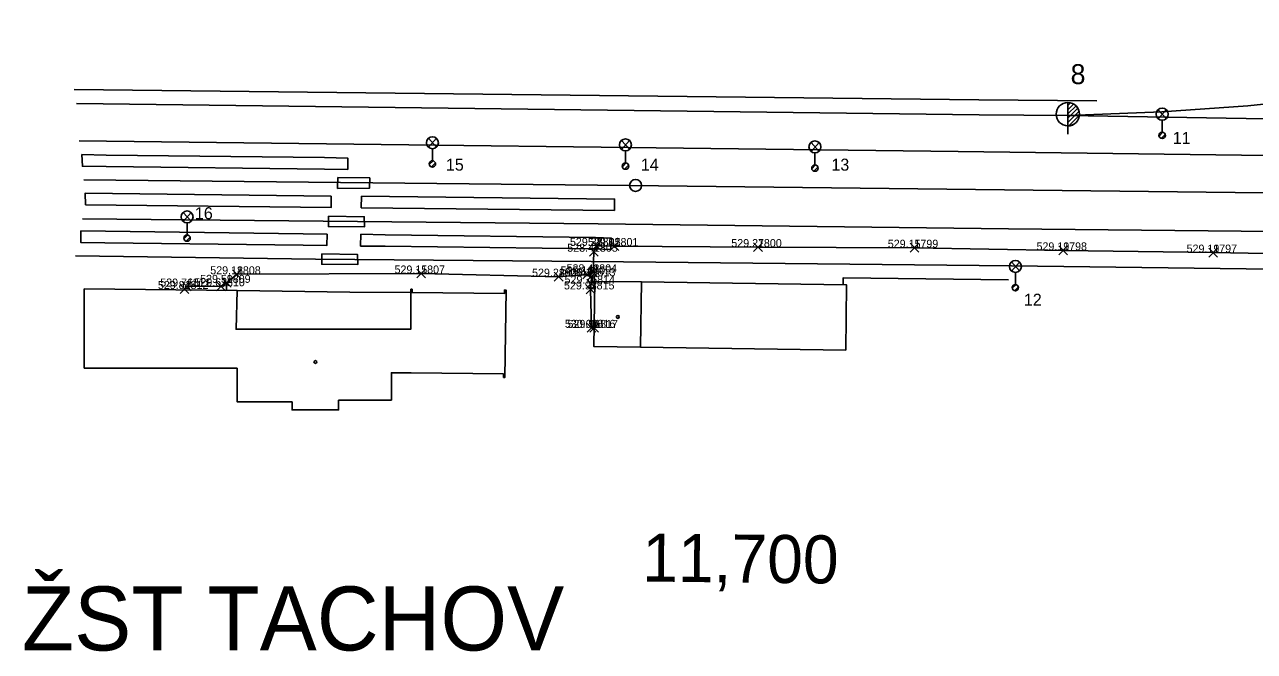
# Model space of a CAD drawing. Extents: x -874058 to -854960, y -10531873 to -1049126.
# Drawn here: x -874058 to -873904.3, y -1055491.8 to -1055413.5 of the extents above; entities that cross this region are included whole.
import ezdxf

# ---------------------------------------------------------------- set-up
doc = ezdxf.new("R2010")
doc.units = 0
for name, color, linetype in [('Vrstva 1', 7, 'Continuous'), ('Vrstva 13', 7, 'Continuous'), ('Vrstva 2', 7, 'Continuous'), ('Vrstva 23', 7, 'Continuous'), ('Vrstva 25', 7, 'Continuous'), ('Vrstva 28', 7, 'Continuous'), ('Vrstva 32', 7, 'Continuous'), ('Vrstva 35', 7, 'Continuous'), ('Vrstva 51', 7, 'Continuous'), ('Vrstva 52', 7, 'Continuous'), ('Vrstva 57', 7, 'Continuous'), ('Vrstva 60', 7, 'Continuous'), ('Vrstva 61', 7, 'Continuous'), ('Vrstva 7', 7, 'Continuous')]:
    doc.layers.add(name, color=color, linetype=linetype)

msp = doc.modelspace()

# ---------------------------------------------------------------- linework, layer by layer
at = {"layer": 'Vrstva 1'}
for points in [[(-873815.18, -1055413.48), (-873832.55, -1055415.22), (-873845.62, -1055416.69), (-873859.57, -1055418.29), (-873878.44, -1055420.61), (-873894.93, -1055422.54), (-873905.16, -1055423.61), (-873915.91, -1055424.4), (-873927.58, -1055424.84), (-873938.71, -1055424.74)], [(-873938.71, -1055424.74), (-874051.5, -1055423.34)], [(-873927.58, -1055424.84), (-873900.45, -1055425.31), (-873892.13, -1055425.7), (-873880.59, -1055426.63), (-873873.55, -1055427.3), (-873854.79, -1055429.58), (-873843.62, -1055431.39), (-873833.71, -1055432.56), (-873816.9, -1055434.47), (-873807.04, -1055435.55), (-873783.51, -1055438.28), (-873772.32, -1055439.75), (-873753.41, -1055441.11), (-873741.16, -1055441.25), (-873729.15, -1055441.64)], [(-874051.14, -1055428), (-873941.33, -1055429.34)], [(-873941.33, -1055429.34), (-873899.48, -1055429.88), (-873880.58, -1055430.11), (-873854.97, -1055431.05), (-873833.71, -1055432.56)], [(-874050.57, -1055432.88), (-873982.4, -1055433.59), (-873820.31, -1055435.48)], [(-873753.41, -1055441.11), (-873775.14, -1055440.87), (-873797, -1055440.56), (-873819.76, -1055440.22), (-873860.62, -1055439.87), (-873897.65, -1055439.39), (-873935.07, -1055438.98), (-873986.31, -1055438.38), (-874050.76, -1055437.73)], [(-873737.8, -1055445.87), (-873747.46, -1055445.67), (-873767.6, -1055445.41), (-873858.85, -1055444.62), (-873898.81, -1055444.08), (-873934.67, -1055443.63), (-873987.18, -1055443.07), (-874021.63, -1055442.79), (-874051.6, -1055442.39)]]:
    msp.add_lwpolyline(points, dxfattribs=at)
at = {"layer": 'Vrstva 13'}
for points in [[(-874051.78, -1055421.58), (-873938.77, -1055422.88), (-873924.01, -1055422.99)], [(-873935.05, -1055445.37), (-873955.72, -1055445.13), (-873955.72, -1055446)]]:
    msp.add_lwpolyline(points, dxfattribs=at)
at = {"layer": 'Vrstva 2'}
for p, q in [((-873927.64, -1055426.14), (-873927.64, -1055423.21)), ((-873927.64, -1055423.21), (-873927.64, -1055426.14)), ((-873927.64, -1055423.59), (-873927.31, -1055423.26)), ((-873927.64, -1055424.12), (-873926.92, -1055423.41)), ((-873927.64, -1055424.65), (-873926.62, -1055423.63)), ((-873927.64, -1055425.19), (-873926.39, -1055423.93)), ((-873927.64, -1055425.72), (-873926.23, -1055424.3)), ((-873927.64, -1055426.14), (-873927.64, -1055427.17)), ((-873927.64, -1055426.14), (-873927.64, -1055426.14)), ((-873927.53, -1055426.13), (-873926.19, -1055424.79))]:
    msp.add_line(p, q, dxfattribs=at)
msp.add_circle((-873927.64, -1055424.67), 1.46, dxfattribs=at)
msp.add_arc((-873927.64, -1055424.68), 1.46, 270.0196, 89.9804, dxfattribs=at)
at = {"layer": 'Vrstva 23'}
for points in [[(-873980.92, -1055445.64), (-873986.75, -1055445.59), (-873986.85, -1055453.72), (-873981.04, -1055453.8), (-873980.92, -1055445.64)], [(-873955.4, -1055454.17), (-873955.28, -1055446.01), (-873980.92, -1055445.64)], [(-874031.4, -1055446.72), (-874050.55, -1055446.49)], [(-874009.74, -1055446.97), (-874017.33, -1055446.9), (-874031.4, -1055446.72)], [(-874009.57, -1055446.53), (-874009.74, -1055446.53)], [(-873998.01, -1055446.64), (-873998.01, -1055447.08), (-874009.57, -1055446.97), (-874009.57, -1055446.53)], [(-873998.14, -1055457.57), (-873997.96, -1055457.57), (-873997.83, -1055446.65), (-873998.01, -1055446.64)], [(-873955.4, -1055454.17), (-873981.04, -1055453.8)], [(-873998.13, -1055457.13), (-874009.69, -1055456.99)], [(-873998.13, -1055457.13), (-873998.14, -1055457.57)]]:
    msp.add_lwpolyline(points, dxfattribs=at)
at = {"layer": 'Vrstva 25'}
for p, q in [((-873916.35, -1055424.11), (-873915.36, -1055425.23)), ((-873916.34, -1055425.24), (-873915.35, -1055424.12)), ((-873915.86, -1055425.42), (-873915.86, -1055426.92)), ((-874007.52, -1055427.68), (-874006.53, -1055428.79)), ((-874007.51, -1055428.81), (-874006.53, -1055427.69)), ((-873916.25, -1055427.4), (-873915.78, -1055426.93)), ((-873915.98, -1055427.7), (-873915.48, -1055427.2)), ((-874007.03, -1055428.99), (-874007.03, -1055430.49)), ((-873983.4, -1055427.95), (-873982.41, -1055429.06)), ((-873983.39, -1055429.08), (-873982.41, -1055427.96)), ((-873982.91, -1055429.26), (-873982.91, -1055430.76)), ((-873959.73, -1055428.2), (-873958.74, -1055429.31)), ((-873959.72, -1055429.33), (-873958.73, -1055428.21)), ((-874007.42, -1055430.97), (-874006.95, -1055430.5)), ((-874007.15, -1055431.27), (-874006.65, -1055430.77)), ((-873983.3, -1055431.24), (-873982.83, -1055430.77)), ((-873959.24, -1055429.51), (-873959.24, -1055431.01)), ((-873983.03, -1055431.54), (-873982.53, -1055431.04)), ((-873959.63, -1055431.49), (-873959.16, -1055431.02)), ((-873959.36, -1055431.79), (-873958.86, -1055431.29)), ((-874038.17, -1055436.95), (-874037.18, -1055438.06)), ((-874038.16, -1055438.08), (-874037.18, -1055436.96)), ((-874037.68, -1055438.26), (-874037.68, -1055439.76)), ((-874038.07, -1055440.24), (-874037.6, -1055439.77)), ((-874037.8, -1055440.54), (-874037.3, -1055440.04)), ((-873934.69, -1055443.14), (-873933.7, -1055444.26)), ((-873934.68, -1055444.27), (-873933.7, -1055443.15)), ((-873934.2, -1055444.45), (-873934.2, -1055445.95)), ((-873934.59, -1055446.43), (-873934.12, -1055445.96)), ((-873934.32, -1055446.73), (-873933.82, -1055446.23))]:
    msp.add_line(p, q, dxfattribs=at)
for centre, radius in [((-873915.86, -1055424.67), 0.749), ((-874007.03, -1055428.24), 0.749), ((-873915.86, -1055427.32), 0.4), ((-873915.86, -1055427.32), 0.4), ((-873982.91, -1055428.51), 0.749), ((-873959.24, -1055428.76), 0.749), ((-874007.03, -1055430.89), 0.4), ((-874007.03, -1055430.89), 0.4), ((-873982.91, -1055431.16), 0.4), ((-873982.91, -1055431.16), 0.4), ((-873959.24, -1055431.41), 0.4), ((-873959.24, -1055431.41), 0.4), ((-874037.68, -1055437.51), 0.749), ((-874037.68, -1055440.16), 0.4), ((-874037.68, -1055440.16), 0.4), ((-873934.2, -1055443.7), 0.749), ((-873934.2, -1055446.35), 0.4), ((-873934.2, -1055446.35), 0.4)]:
    msp.add_circle(centre, radius, dxfattribs=at)
at = {"layer": 'Vrstva 28'}
msp.add_lwpolyline([(-874032.72, -1055445.75), (-874032.76, -1055446.68)], dxfattribs=at)
at = {"layer": 'Vrstva 32'}
for points in [[(-873987.69, -1055444.7), (-873986.94, -1055444.43), (-873986.85, -1055441.86), (-873986.52, -1055441.13), (-873984.27, -1055441.15), (-873966.36, -1055441.28), (-873946.81, -1055441.36), (-873928.23, -1055441.69), (-873909.48, -1055441.97), (-873892.04, -1055442.27)], [(-874037.99, -1055446.52), (-874037.7, -1055446.21), (-874033.44, -1055446.18), (-874032.72, -1055445.75), (-874031.45, -1055444.68), (-874008.43, -1055444.58), (-873991.25, -1055444.98), (-873987.69, -1055444.7)], [(-873986.82, -1055451.38), (-873987.15, -1055451.37), (-873987.26, -1055446.57), (-873987.19, -1055445.84), (-873987.14, -1055444.92), (-873987.69, -1055444.7)]]:
    msp.add_lwpolyline(points, dxfattribs=at)
at = {"layer": 'Vrstva 35'}
msp.add_lwpolyline([(-873986.94, -1055444.43), (-873986.85, -1055441.86)], dxfattribs=at)
at = {"layer": 'Vrstva 51'}
for points in [[(-874047.79, -1055429.78), (-874050.81, -1055429.72), (-874050.76, -1055431.17), (-874047.78, -1055431.21), (-874020.51, -1055431.53), (-874017.6, -1055431.58), (-874017.61, -1055430.15), (-874020.5, -1055430.1), (-874047.79, -1055429.78)], [(-874018.86, -1055432.58), (-874018.88, -1055433.94), (-874014.87, -1055433.9), (-874014.86, -1055432.63), (-874018.86, -1055432.58)], [(-874050.37, -1055436.01), (-874050.39, -1055434.54), (-874019.67, -1055434.91)], [(-874050.37, -1055436.01), (-874019.69, -1055436.35), (-874019.67, -1055434.91)], [(-873984.27, -1055436.7), (-874015.92, -1055436.36), (-874015.87, -1055434.93), (-873984.26, -1055435.29), (-873984.27, -1055436.7)], [(-874020.02, -1055437.43), (-874015.54, -1055437.5), (-874015.52, -1055438.75), (-874020.03, -1055438.71), (-874020.02, -1055437.43)], [(-874050.93, -1055439.25), (-874023.18, -1055439.62), (-874020.19, -1055439.67), (-874020.23, -1055441.09), (-874023.17, -1055441.04), (-874047.96, -1055440.75), (-874050.93, -1055440.72), (-874050.93, -1055439.25)], [(-873986.64, -1055440.09), (-873984.67, -1055440.15), (-873984.73, -1055441.59), (-873986.76, -1055441.5), (-874012.93, -1055441.16), (-874016, -1055441.15), (-874015.97, -1055439.68), (-874012.94, -1055439.73), (-873986.64, -1055440.09)], [(-874020.85, -1055442.14), (-874016.37, -1055442.21), (-874016.35, -1055443.46), (-874020.86, -1055443.42), (-874020.85, -1055442.14)]]:
    msp.add_lwpolyline(points, dxfattribs=at)
at = {"layer": 'Vrstva 52'}
for points in [[(-874050.55, -1055446.49), (-874050.55, -1055456.42)], [(-874031.4, -1055446.72), (-874031.56, -1055451.55), (-874009.74, -1055451.55), (-874009.74, -1055446.53)], [(-874050.55, -1055456.42), (-874031.4, -1055456.42)], [(-874031.4, -1055456.42), (-874031.4, -1055460.62), (-874024.56, -1055460.62), (-874024.56, -1055461.62), (-874018.75, -1055461.62), (-874018.75, -1055460.43), (-874012.14, -1055460.43)], [(-874012.14, -1055460.43), (-874012.14, -1055456.99), (-874009.69, -1055456.99)]]:
    msp.add_lwpolyline(points, dxfattribs=at)
at = {"layer": 'Vrstva 57'}
for centre in [(-873983.86, -1055450.01), (-874021.65, -1055455.64)]:
    msp.add_circle(centre, 0.175, dxfattribs=at)
at = {"layer": 'Vrstva 60'}
for p, q in [((-873987.4, -1055442.41), (-873986.3, -1055441.31)), ((-873986.3, -1055442.41), (-873987.4, -1055441.31)), ((-873987.07, -1055441.68), (-873985.97, -1055440.58)), ((-873985.97, -1055441.68), (-873987.07, -1055440.58)), ((-873984.82, -1055441.7), (-873983.72, -1055440.6)), ((-873983.72, -1055441.7), (-873984.82, -1055440.6)), ((-873966.91, -1055441.83), (-873965.81, -1055440.73)), ((-873965.81, -1055441.83), (-873966.91, -1055440.73)), ((-873947.36, -1055441.91), (-873946.26, -1055440.81)), ((-873946.26, -1055441.91), (-873947.36, -1055440.81)), ((-873928.78, -1055442.24), (-873927.68, -1055441.14)), ((-873927.68, -1055442.24), (-873928.78, -1055441.14)), ((-873910.03, -1055442.52), (-873908.93, -1055441.42)), ((-873908.93, -1055442.52), (-873910.03, -1055441.42)), ((-874032, -1055445.23), (-874030.9, -1055444.13)), ((-874030.9, -1055445.23), (-874032, -1055444.13)), ((-874008.98, -1055445.13), (-874007.88, -1055444.03)), ((-874007.88, -1055445.13), (-874008.98, -1055444.03)), ((-873991.8, -1055445.53), (-873990.7, -1055444.43)), ((-873990.7, -1055445.53), (-873991.8, -1055444.43)), ((-873988.24, -1055445.25), (-873987.14, -1055444.15)), ((-873987.14, -1055445.25), (-873988.24, -1055444.15)), ((-873987.69, -1055445.47), (-873986.59, -1055444.37)), ((-873986.59, -1055445.47), (-873987.69, -1055444.37)), ((-873987.49, -1055444.98), (-873986.39, -1055443.88)), ((-873986.39, -1055444.98), (-873987.49, -1055443.88)), ((-874038.54, -1055447.07), (-874037.44, -1055445.97)), ((-874037.44, -1055447.07), (-874038.54, -1055445.97)), ((-874038.25, -1055446.76), (-874037.15, -1055445.66)), ((-874037.15, -1055446.76), (-874038.25, -1055445.66)), ((-874033.99, -1055446.73), (-874032.89, -1055445.63)), ((-874032.89, -1055446.73), (-874033.99, -1055445.63)), ((-874033.27, -1055446.3), (-874032.17, -1055445.2)), ((-874032.17, -1055446.3), (-874033.27, -1055445.2)), ((-873987.81, -1055447.12), (-873986.71, -1055446.02)), ((-873986.71, -1055447.12), (-873987.81, -1055446.02)), ((-873987.74, -1055446.39), (-873986.64, -1055445.29)), ((-873986.64, -1055446.39), (-873987.74, -1055445.29)), ((-873987.7, -1055451.92), (-873986.6, -1055450.82)), ((-873986.6, -1055451.92), (-873987.7, -1055450.82)), ((-873987.37, -1055451.93), (-873986.27, -1055450.83)), ((-873986.27, -1055451.93), (-873987.37, -1055450.83))]:
    msp.add_line(p, q, dxfattribs=at)
at = {"layer": 'Vrstva 7'}
msp.add_circle((-873981.64, -1055433.58), 0.75, dxfattribs=at)

# ---------------------------------------------------------------- texts
at = {"layer": 'Vrstva 2'}
msp.add_text('8', height=2.5, dxfattribs=at).set_placement((-873927.3, -1055420.92))
at = {"layer": 'Vrstva 23'}
msp.add_text('ŽST TACHOV', height=8, dxfattribs=at).set_placement((-874058.32, -1055491.69))
at = {"layer": 'Vrstva 25'}
for s, p in [('11', (-873914.54, -1055428.39)), ('15', (-874005.34, -1055431.73)), ('14', (-873980.99, -1055431.73)), ('13', (-873957.18, -1055431.73)), ('16', (-874036.7, -1055437.8)), ('12', (-873933.14, -1055448.61))]:
    msp.add_text(s, height=1.5, dxfattribs=at).set_placement(p)
at = {"layer": 'Vrstva 60'}
for s, p in [('1803', (-873986.85, -1055441.86)), ('1802', (-873986.52, -1055441.13)), ('1801', (-873984.27, -1055441.15)), ('1800', (-873966.36, -1055441.28)), ('1799', (-873946.81, -1055441.36)), ('1798', (-873928.23, -1055441.69)), ('1797', (-873909.48, -1055441.97)), ('1808', (-874031.45, -1055444.68)), ('1807', (-874008.43, -1055444.58)), ('1806', (-873991.25, -1055444.98)), ('1805', (-873987.69, -1055444.7)), ('1813', (-873987.14, -1055444.92)), ('1804', (-873986.94, -1055444.43)), ('1812', (-874037.99, -1055446.52)), ('1811', (-874037.7, -1055446.21)), ('1810', (-874033.44, -1055446.18)), ('1809', (-874032.72, -1055445.75)), ('1815', (-873987.26, -1055446.57)), ('1814', (-873987.19, -1055445.84)), ('1816', (-873987.15, -1055451.37)), ('1817', (-873986.82, -1055451.38))]:
    msp.add_text(s, height=1, dxfattribs=at).set_placement(p)
at = {"layer": 'Vrstva 61'}
for s, p in [('528.47 ', (-873990.18, -1055441.86)), ('529.38 ', (-873989.85, -1055441.13)), ('529.25 ', (-873987.6, -1055441.15)), ('529.27 ', (-873969.69, -1055441.28)), ('529.15 ', (-873950.14, -1055441.36)), ('529.19 ', (-873931.56, -1055441.69)), ('529.19 ', (-873912.81, -1055441.97)), ('529.18 ', (-874034.78, -1055444.68)), ('529.15 ', (-874011.76, -1055444.58)), ('529.28 ', (-873994.58, -1055444.98)), ('529.16 ', (-873991.02, -1055444.7)), ('529.19 ', (-873990.47, -1055444.92)), ('528.42 ', (-873990.27, -1055444.43)), ('529.84 ', (-874041.32, -1055446.52)), ('529.76 ', (-874041.03, -1055446.21)), ('529.62 ', (-874036.77, -1055446.18)), ('529.59 ', (-874036.05, -1055445.75)), ('529.93 ', (-873990.59, -1055446.57)), ('529.76 ', (-873990.52, -1055445.84)), ('530.03 ', (-873990.48, -1055451.37)), ('529.96 ', (-873990.15, -1055451.38))]:
    msp.add_text(s, height=1, dxfattribs=at).set_placement(p)
at = {"layer": 'Vrstva 7'}
msp.add_text('11,700', height=6, rotation=359.389, dxfattribs=at).set_placement((-873980.85, -1055483.07))

doc.saveas('drawing.dxf')
